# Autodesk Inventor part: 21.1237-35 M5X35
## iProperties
Created: 2006-02
Part Number: 21.1237-35 M5X35
Material: Steel, Mild
Description: Cylinder Head Cap Screw
Document SubType Name: Modeling
Standard: DIN 912
Designer: Andy Moles
Standards Organization: DIN
Language: en-US
Size Designation: M5 x 35
Categories: <MemberInstance><Categories><Category DisplayName="Fasteners" InternalName="e4da775c-781d-43d5-af7c-5136215cf5a6" Mnemonic="FSTN"><Category DisplayName="Bolts"
Density: 7.86 g/cm^3
IsCustomPart: 1
Author: Andy Moles
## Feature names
1. Body [Revolution]
2. Slot [Extrusion]
3. Fillet1
4. Chamfer1
